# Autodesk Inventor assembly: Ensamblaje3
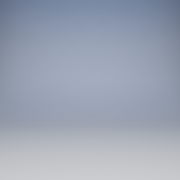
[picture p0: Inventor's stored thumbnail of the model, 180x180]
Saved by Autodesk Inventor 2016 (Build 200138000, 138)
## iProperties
Created: 2016-06
Part Number: Ensamblaje3
Material: Genérico
Document SubType Name: Assembly
Designer: adm
Author: adm
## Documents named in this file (1)
- C:\Users\adm\Desktop\proyecto del profe. valcarcel\trabajo3\Ensamblaje3.iam
